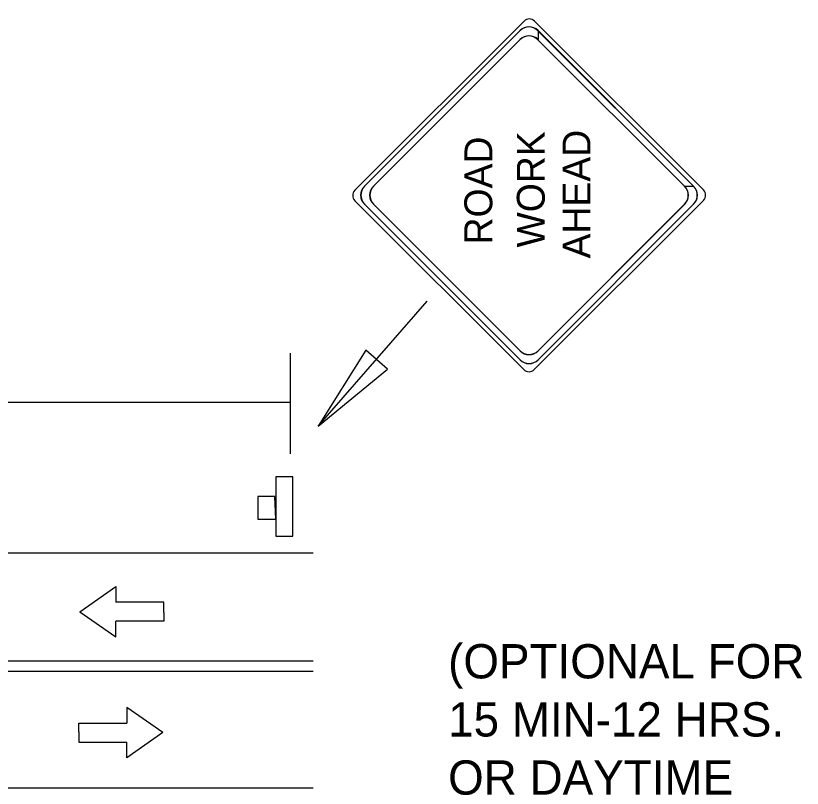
# Model space of a CAD drawing. Extents: x 1531.4 to 1538.6, y 1528.5 to 1539.8.
# Drawn here: x 1536.717 to 1538.094, y 1535.949 to 1537.302 of the extents above; entities that cross this region are included whole.
import ezdxf

# ---------------------------------------------------------------- set-up
doc = ezdxf.new("R2010")
doc.units = 0
for name, color, linetype in [('DETL-DIMS', 7, 'Continuous'), ('DETL-LINE', 7, 'Continuous'), ('DETL-NOTE', 7, 'Continuous'), ('USER-BORD', 7, 'Continuous')]:
    doc.layers.add(name, color=color, linetype=linetype)

# ---------------------------------------------------------------- blocks, each defined once
blk = doc.blocks.new('DIR')
at = {"layer": 'USER-BORD'}
for p, q in [((0, 0.0001), (-0.0034, -0.0048)), ((0, 0.0001), (0.0034, -0.0048)), ((-0.0034, -0.0048), (-0.0013, -0.0048)), ((-0.0013, -0.0113), (-0.0013, -0.0048)), ((0.0034, -0.0048), (0.0013, -0.0048)), ((0.0013, -0.0113), (0.0013, -0.0048)), ((-0.0001, -0.0113), (-0.0013, -0.0113)), ((-0.0001, -0.0113), (0.0001, -0.0113)), ((0.0001, -0.0113), (0.0013, -0.0113))]:
    blk.add_line(p, q, dxfattribs=at)
blk = doc.blocks.new('SIGN')
at = {"layer": 'USER-BORD'}
for points in [[(-0.0013, 0.0018), (0.0011, 0.0019), (0.0011, 0.0037), (-0.0013, 0.0037)], [(-0.0031, 0.0018), (-0.0031, 0), (0.0032, 0), (0.0032, 0.0018)]]:
    blk.add_lwpolyline(points, close=True, dxfattribs=at)
blk = doc.blocks.new('R-BRD0')
at = {"layer": 'USER-BORD'}
for p, q in [((1.415, 2.9962), (-1.4125, 2.9962)), ((-1.5, 2.9087), (-1.5, 0.0875)), ((-1.3, 2.9499), (1.3, 2.9499)), ((1.5025, 0.0875), (1.5025, 2.9087)), ((-1.45, 0.1998), (-1.45, 2.7999)), ((1.2249, 2.8751), (-1.225, 2.8751)), ((1.45, 2.7999), (1.45, 0.1998)), ((-1.375, 2.7251), (-1.375, 0.2749)), ((1.3749, 0.2749), (1.3749, 2.7251)), ((-1.225, 0.1249), (1.2249, 0.1249)), ((-1.4125, 0), (1.415, 0)), ((1.3, 0.0498), (-1.3, 0.0498))]:
    blk.add_line(p, q, dxfattribs=at)
for centre, radius, start, end in [((-1.4125, 2.9087), 0.0875, 90, 180), ((1.415, 2.9087), 0.0875, 0, 90), ((-1.3, 2.7999), 0.15, 90, 180), ((1.3, 2.7999), 0.15, 0, 90), ((-1.225, 2.7251), 0.15, 90, 180), ((1.2249, 2.7251), 0.15, 0, 90), ((-1.3, 0.1998), 0.15, 180, 270), ((-1.225, 0.2749), 0.15, 180, 270), ((1.2249, 0.2749), 0.15, 270, 0), ((1.3, 0.1998), 0.15, 270, 0), ((-1.4125, 0.0875), 0.0875, 180, 270), ((1.415, 0.0875), 0.0875, 270, 0)]:
    blk.add_arc(centre, radius, start, end, dxfattribs=at)
blk = doc.blocks.new('W-BRD0')
at = {"layer": 'USER-BORD', "rotation": 45}
blk.add_blockref('R-BRD0', (1.0448, 1.0213), dxfattribs=at)

msp = doc.modelspace()

# ---------------------------------------------------------------- linework, layer by layer
at = {"layer": 'DETL-DIMS'}
for p, q in [((1537.2467, 1536.5835), (1537.4375, 1536.8022)), ((1537.1973, 1536.7114), (1537.1973, 1536.5349)), ((1535.3511, 1536.6255), (1537.1973, 1536.6255))]:
    msp.add_line(p, q, dxfattribs=at)
msp.add_lwpolyline([(1537.3679, 1536.6831), (1537.3298, 1536.7167), (1537.2467, 1536.5835)], close=True, dxfattribs=at)
at = {"layer": 'DETL-LINE'}
for p, q in [((1537.6002, 1537.2764), (1537.3278, 1537.0037)), ((1537.6317, 1537.2764), (1537.9042, 1537.0037)), ((1537.9042, 1537.0037), (1537.6317, 1537.2764)), ((1537.3434, 1537.0037), (1537.6002, 1537.2606)), ((1537.3278, 1536.9723), (1537.6002, 1536.6996)), ((1537.6002, 1536.7153), (1537.3434, 1536.9723)), ((1537.8885, 1536.9723), (1537.6317, 1536.7153)), ((1537.6317, 1536.6996), (1537.9042, 1536.9723)), ((1537.2377, 1536.361), (1535.5657, 1536.361)), ((1535.6458, 1536.1723), (1537.2377, 1536.1723)), ((1535.6458, 1536.1542), (1537.2377, 1536.1542)), ((1537.2377, 1535.9492), (1535.5657, 1535.9492))]:
    msp.add_line(p, q, dxfattribs=at)
msp.add_lwpolyline([(1537.8885, 1537.0037), (1537.9042, 1537.0037), (1537.6317, 1537.2764), (1537.6317, 1537.2606)], dxfattribs=at)
for centre, start_param, end_param in [((1537.616, 1537.2607), 5.497787, 7.068583), ((1537.616, 1537.245), 5.497787, 7.068583), ((1537.3435, 1536.988), 0.785398, 2.356194), ((1537.3592, 1536.988), 0.785398, 2.356194), ((1537.8728, 1536.988), 3.926991, 5.497787), ((1537.8885, 1536.988), 3.926991, 5.497787), ((1537.616, 1536.7311), 2.356194, 3.926991), ((1537.616, 1536.7154), 2.356194, 3.926991)]:
    msp.add_ellipse(centre, major_axis=(0, 0.0222), ratio=0.999437, start_param=start_param, end_param=end_param, dxfattribs=at)

# ---------------------------------------------------------------- block references
at = {"layer": 'DETL-LINE', "xscale": 0.14822291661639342, "yscale": 0.14830634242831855}
msp.add_blockref('W-BRD0', (1537.6182, 1536.6792), dxfattribs=at)
at = {"layer": 'DETL-LINE'}
for name, p, xscale, yscale, rotation in [('SIGN', (1537.2019, 1536.442), 16.482020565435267, 16.482020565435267, 89.99999999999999), ('DIR', (1536.8303, 1536.2584), 12.922428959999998, 12.922428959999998, 90), ('DIR', (1536.9733, 1536.0466), 12.922428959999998, 12.922428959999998, -90.00000000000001)]:
    msp.add_blockref(name, p, dxfattribs=dict(at, xscale=xscale, yscale=yscale, rotation=rotation))

# ---------------------------------------------------------------- texts
for s, p in [('WORK', (1537.6434, 1536.8965)), ('AHEAD', (1537.7234, 1536.8772)), ('ROAD ', (1537.5515, 1536.9018))]:
    msp.add_text(s, height=0.04891, rotation=90, dxfattribs=at).set_placement(p)
at = {"layer": 'DETL-NOTE'}
for s, p in [('(OPTIONAL FOR', (1537.4741, 1536.1416)), ('15 MIN-12 HRS. ', (1537.4741, 1536.0398)), ('OR DAYTIME', (1537.4741, 1535.938))]:
    msp.add_text(s, height=0.06, dxfattribs=at).set_placement(p)

doc.saveas('drawing.dxf')
